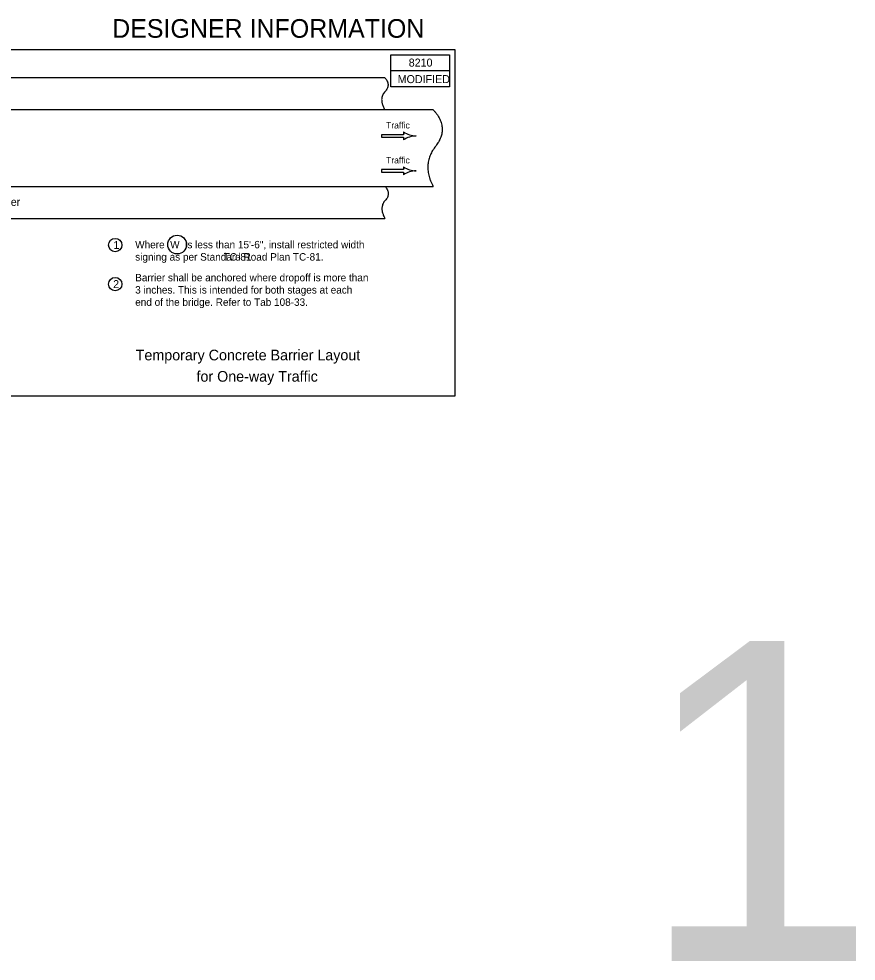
# Model space of a CAD drawing. Extents: x 8045 to 81668, y 6217 to 16762.
# Drawn here: x 10335 to 11904, y 10409 to 12176 of the extents above; entities that cross this region are included whole.
import ezdxf

# ---------------------------------------------------------------- set-up
doc = ezdxf.new("R2010")
doc.units = 0
for name, color, linetype in [('dsnNonPlotable', 7, 'Continuous'), ('dsnShtPlotShapeBatchPrint', 7, 'Continuous'), ('dsnStdBlockModified', 7, 'Continuous'), ('dsnStdBorder', 7, 'Continuous'), ('dsnStdLineWork', 7, 'Continuous'), ('Level 1', 7, 'Continuous'), ('Level 2', 7, 'Continuous'), ('Level 3', 7, 'Continuous'), ('Level 5', 7, 'Continuous')]:
    doc.layers.add(name, color=color, linetype=linetype)

msp = doc.modelspace()

# ---------------------------------------------------------------- linework, layer by layer
at = {"layer": 'dsnNonPlotable'}
for p, q in [((9672.2, 12065.5), (11020.7, 12065.5)), ((9779.7, 12005.5), (11111, 12005.5)), ((11055.4, 11963.6), (11055.4, 11958.3)), ((11055.4, 11958.3), (11014.1, 11958.3)), ((11014.1, 11958.3), (11014.1, 11953.8)), ((11014.1, 11953.8), (11055.4, 11953.8)), ((11055.4, 11953.8), (11055.4, 11948.6)), ((11079.3, 11956.1), (11079.3, 11956.1)), ((11055.4, 11892.9), (11014.1, 11892.9)), ((11014.1, 11892.9), (11014.1, 11888.4)), ((11014.1, 11888.4), (11055.4, 11888.4)), ((11055.4, 11898.1), (11055.4, 11892.9)), ((11055.4, 11888.4), (11055.4, 11883.1)), ((11079.3, 11890.6), (11079.3, 11890.6)), ((9642.2, 11861.5), (11111, 11861.5)), ((9672.2, 11801.5), (11020.7, 11801.5))]:
    msp.add_line(p, q, dxfattribs=at)
for centre, radius in [((10631.5, 11752.4), 17.6), ((10515.4, 11751.6), 12.5), ((10515.4, 11678.3), 12.5)]:
    msp.add_circle(centre, radius, dxfattribs=at)
for centre, start, end in [((11081.3, 12004.4), 237.618, 267.648), ((11081.3, 11907.8), 92.352, 122.382), ((11081.3, 11939), 237.618, 267.648), ((11081.3, 11842.3), 92.352, 122.382)]:
    msp.add_arc(centre, 48.4, start, end, dxfattribs=at)
for points in [[(11020.7, 12065.5), (11032.5, 12051.4), (11008.8, 12026.4), (11020.2, 12005.5)], [(11111, 12005.5), (11142.5, 11971.1), (11089.1, 11903), (11111, 11861.5)], [(11021.1, 11861.5), (11032.9, 11847.4), (11009.3, 11822.3), (11020.7, 11801.5)]]:
    msp.add_open_spline(points, degree=2, dxfattribs=at)
at = {"layer": 'dsnShtPlotShapeBatchPrint'}
msp.add_lwpolyline([(11142, 12108.1), (11142, 12048.1), (11032, 12048.1), (11032, 12108.1), (11142, 12108.1), (11142, 12078.1), (11032, 12078.1)], dxfattribs=at)
at = {"layer": 'dsnStdBlockModified'}
for p, q in [((8047, 12118.1), (11152, 12118.1)), ((11152, 12118.1), (11152, 11468.1))]:
    msp.add_line(p, q, dxfattribs=at)
at = {"layer": 'dsnStdBorder'}
msp.add_line((11152, 11468.1), (8047, 11468.1), dxfattribs=at)
at = {"layer": 'Level 2'}
msp.add_line((11152, 12118.1), (11152, 12118.1), dxfattribs=at)

# ---------------------------------------------------------------- texts
at = {"layer": 'dsnStdLineWork'}
for s, height, p in [('Temporary Concrete Barrier Layout', 20, (10553.8, 11535.4)), ('for One-way Traffic', 20, (10667.7, 11495.4)), ('1', 600, (11496.6, 10409.2))]:
    msp.add_text(s, height=height, dxfattribs=at).set_placement(p)
at = {"layer": 'Level 1'}
msp.add_text('DESIGNER INFORMATION', height=35, dxfattribs=at).set_placement((10509.6, 12140.1))
at = {"layer": 'Level 3'}
for s, p in [('8210', (11065.3, 12086.1)), ('MODIFIED', (11044.6, 12055.1))]:
    msp.add_text(s, height=15, dxfattribs=at).set_placement(p)
at = {"layer": 'Level 5'}
for s, height, p in [('Traffic', 12, (11022.8, 11970.1)), ('Traffic', 12, (11022.8, 11904.6)), ('Shoulder', 15, (10257.2, 11824.9)), ('1', 15, (10512, 11744.1)), ('Where  W  is less than 15\'-6", install restricted width', 14, (10552.8, 11745.4)), ('signing as per Standard Road Plan TC-81.', 14, (10552.8, 11722.4)), ('                                TC-81', 14, (10552.1, 11722.4)), ('Barrier shall be anchored where dropoff is more than', 14, (10552.8, 11683.6)), ('2', 15, (10511.4, 11670.8)), ('3 inches. This is intended for both stages at each', 14, (10552.8, 11660.6)), ('end of the bridge. Refer to Tab 108-33.', 14, (10552.8, 11637.6))]:
    msp.add_text(s, height=height, dxfattribs=at).set_placement(p)

doc.saveas('drawing.dxf')
